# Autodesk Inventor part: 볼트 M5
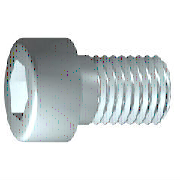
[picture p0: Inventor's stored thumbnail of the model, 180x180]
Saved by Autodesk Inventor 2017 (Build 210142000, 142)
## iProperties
IsCustomPart: 1
Created: 2012-02
Part Number: 볼트 M5
Material: 강철, 연강
Description: 6각머리 태핑 나사
Document SubType Name: Modeling
Standard: KS B 1003
Designer: mduedu
Standards Organization: KS
Language: ko-KR
Size Designation: M 5 x 16
Categories: <MemberInstance><Categories><Category DisplayName="조임쇠" InternalName="e4da775c-781d-43d5-af7c-5136215cf5a6" Mnemonic="FSTN"><Category DisplayName="볼트" InternalN
Density: 1 g/cm^3
Appearance: 강철
Author: mduedu
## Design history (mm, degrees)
sketch "스케치1"
  geometry: L1 (-1.167, 0)-(16, 0); L2 (16, 0)-(16, 2.5); L3 (16, 2.5)-(2, 2.5); L4 (2, 2.5)-(1.509, 2.5); L5 (1.509, 2.5)-(0, 2.5); L6 (0, 2.5)-(0, 4.25); L7 (0, 4.25)-(-5, 4.25); L8 (-5, 4.25)-(-5, 2.309); L9 (-5, 2.309)-(-2.5, 2.309); L10 (-2.5, 2.309)-(-1.167, 0); L11 (-9.2, 0)-(20.2, 0) reference; L12 (0, -0.85)-(0, 5.1) reference; L13 (2, 2.5)-(0, 2.5)
  constraints: 22 end point, 6 parallel, 2 collinear, 2 perpendicular, 1 horizontal, 1 point on line
  dimensions: "d1" = 14 distance from line of L3.end L2 (= GEL); "d2" = 0.49086 distance of L4.end L3.end (computed from GAL); "d3" = 5 distance between parallel lines of L8 L6 (= KOH); "d4" = 2.5 distance of L8.end L9.end (= INTI); "d5" = 60 deg angle of L10 L1; "d6" = 5 diameter of L3 L1 (= GD); "d7" = 5 diameter of L5 L1 (= BDM); "d8" = 4.6188 diameter of L9 L1 (= 1.1547 x SW); "d9" = 8.5 diameter of L7 L1 (= KOD); "d26" = 16 distance between parallel lines of L12 L2 (= NLG)
revolve "본체" sketch "스케치1" stored, may be unused: angle "d10" = 90 deg
sketch "스케치2"
  geometry: L1 (0, -5.95)-(0, 5.95) reference; L2 (-5.95, 0)-(5.95, 0) reference; L3 (2.309, 0)-(1.155, -2); L4 (1.155, -2)-(-1.155, -2); L5 (-1.155, -2)-(-2.309, 0); L6 (-2.309, 0)-(-1.155, 2); L7 (-1.155, 2)-(1.155, 2); L8 (1.155, 2)-(2.309, 0); 2 further points
  constraints: 12 end point, 1 coincident, 1 horizontal alignment, 1 point on line, 12 other
extrude "슬롯" join sketch "스케치2" stored distance "d11" = 10; taper "d12" = 0 deg
workplane "Work Plane1"
fillet "Fillet2" dims "d30" = 0.1 (= R)
body "Solid1"
fillet "모깎기1" dims "d17" = 0.5 (= RR)
feature "스레드" dims "d13" = 14 (= GEL), "d14" = 0
chamfer "모따기1" distance "d15" = 0.49076 (= -0.5 x SPD + 0.5 x GD); stored, may be unused: second distance "d16" = 0.49076 (= GUL), angle "d27" = 45 deg
other parameters: "GD" = 5 (= NND) [user parameter; used in 2 equation terms], "NLG" = 16 [user parameter; used in 1 equation term], "GEL" = 14 [user parameter; used in 2 equation terms], "KOD" = 8.5 [user parameter; used in 1 equation term], "KOH" = 5 [user parameter; used in 1 equation term], "INTI" = 2.5 [user parameter; used in 1 equation term], "GAL" = 0.49076 (= 0.61345 x PTC) [user parameter; used in 1 equation term], "GUL" = 0.49076 (= 0.61345 x PTC) [user parameter; used in 1 equation term], "BDM" = 5 (= NND) [user parameter; used in 1 equation term], "SW" = 4 [user parameter; used in 2 equation terms], "RR" = 0.5 [user parameter; used in 1 equation term], "SPD" = 4.01848 (= NND - 1.2269 x PTC) [user parameter; used in 1 equation term], "d19" = 0, "d28" = 0, "d29" = 0, "R" = 0.1 [user parameter; used in 1 equation term], "PHH" = 0.2 [user parameter], "GD1" = 4.01848 (= THREADDIA - 1.2269 x PTC) [user parameter], "THREADDIA" = 5 [user parameter; used in 1 equation term], "FAWI" = 45 deg [user parameter], "TPU" = 12.5 (computed from PTC) [user parameter], "PTC" = 0.8 [user parameter; used in 5 equation terms], "NND" = 5 [user parameter; used in 3 equation terms], "TOA" = 30 deg [user parameter], "E0" = 4.62 (= 1.155 x SW) [user parameter]
